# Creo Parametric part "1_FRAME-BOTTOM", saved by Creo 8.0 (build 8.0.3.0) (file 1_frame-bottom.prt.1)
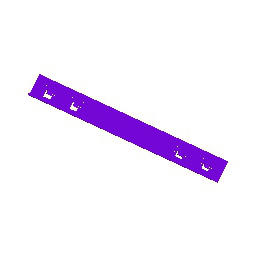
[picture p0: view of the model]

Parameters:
  SMT_DFLT_BEND_REL_LENGTH_TYPE = "Through All"

Other parameters: SMT_UPDATE_BEND_ALLOW_INFO, SMT_THICKNESS, SMT_PART_BEND_ALLOWANCE_FACTOR, SMT_DFLT_BEND_RADIUS, SMT_DFLT_BEND_ANGLE, SMT_DFLT_CRNR_REL_WIDTH, SMT_DFLT_CRNR_REL_DEPTH, SMT_DFLT_BEND_REL_WIDTH, SMT_DFLT_BEND_REL_DEPTH, SMT_DFLT_BEND_REL_LENGTH, SMT_DFLT_BEND_REL_ANGLE, SMT_GAP, SMT_DFLT_EDGE_TREA_WIDTH, SMT_DFLT_MITER_CUT_WIDTH, SMT_DFLT_MITER_CUT_OFFSET

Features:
  1. datum plane "RIGHT"
  2. datum plane "TOP"
  3. datum plane "FRONT"
  4. coordinate system
  5. pattern
  6. cut
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
Layers: 0_ALL_AXIS, 0_ALL_CSYS, 0_ALL_CURVES, 0_ALL_PLANES, 0_ALL_POINTS, 0_ALL_SURFS, FRAME-BOTTOM

Surfaces: 226 plane, 82 cylinder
